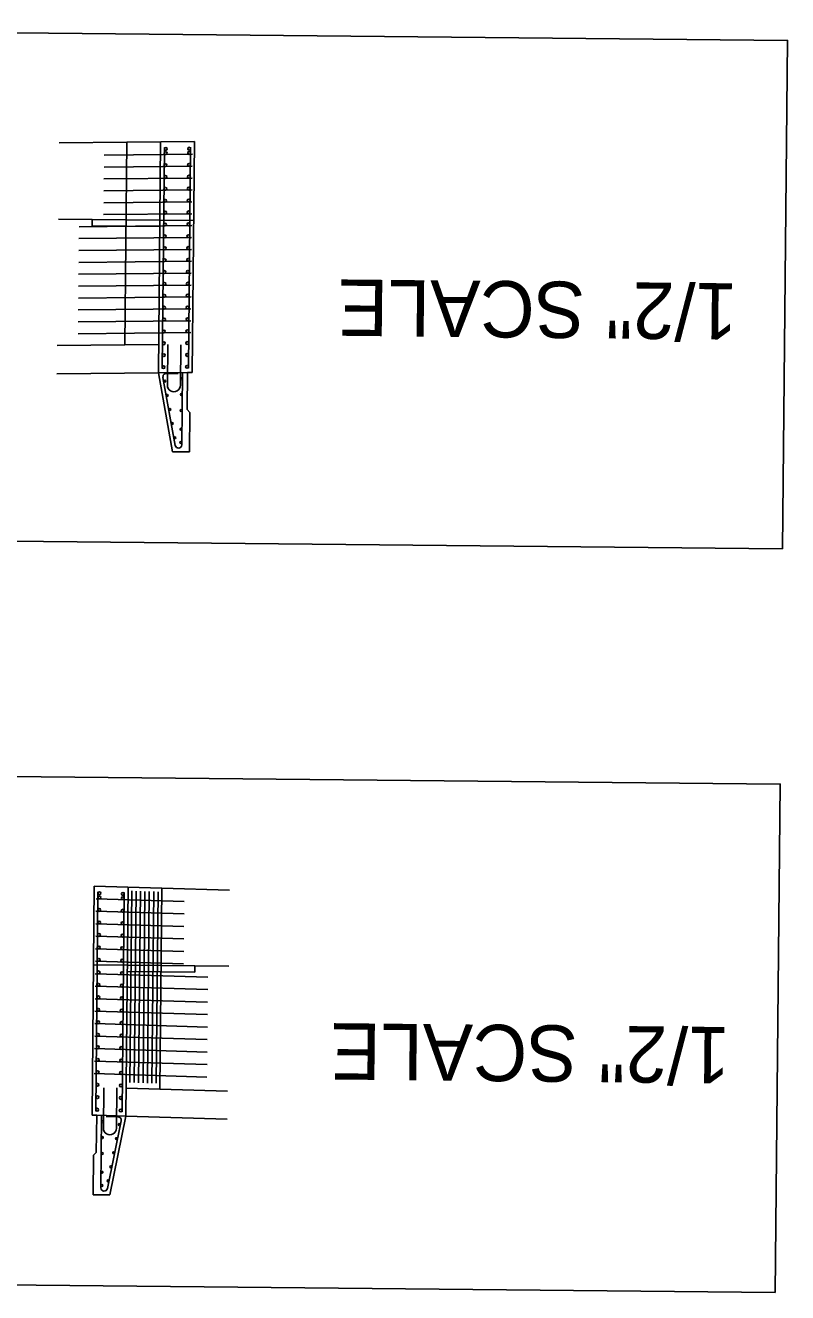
# Model space of a CAD drawing. Extents: x 631918 to 632319, y 373181 to 373282.
# Drawn here: x 631978.4 to 632012.2, y 373182.8 to 373239 of the extents above; entities that cross this region are included whole.
import ezdxf

# ---------------------------------------------------------------- set-up
doc = ezdxf.new("R2010")
doc.units = 0
for name, color, linetype in [('B_Boring', 7, 'Continuous'), ('BD-PROP-COSS', 7, 'Continuous'), ('BD-REMOVE', 7, 'Continuous'), ('R_Border_Scale', 7, 'Continuous'), ('R_Shade Removal', 7, 'Continuous')]:
    doc.layers.add(name, color=color, linetype=linetype)

msp = doc.modelspace()

# ---------------------------------------------------------------- linework, layer by layer
at = {"layer": 'B_Boring'}
for p, q in [((631984.267, 373223.578), (631984.369, 373233.817)), ((631982.822, 373190.59), (631982.923, 373200.757))]:
    msp.add_line(p, q, dxfattribs=at)
at = {"layer": 'BD-PROP-COSS'}
for p, q in [((631981.861, 373233.229), (631985.777, 373233.269)), ((631984.435, 373223.767), (631984.533, 373233.568)), ((631985.602, 373223.777), (631985.699, 373233.58)), ((631981.855, 373232.702), (631985.772, 373232.741)), ((631981.85, 373232.175), (631985.767, 373232.214)), ((631981.845, 373231.648), (631985.761, 373231.687)), ((631981.84, 373231.12), (631985.756, 373231.16)), ((631981.837, 373230.593), (631985.753, 373230.633)), ((631980.748, 373230.055), (631985.748, 373230.105)), ((631980.743, 373229.528), (631985.743, 373229.578)), ((631980.738, 373229.001), (631985.738, 373229.051)), ((631980.733, 373228.474), (631985.732, 373228.524)), ((631980.727, 373227.946), (631985.727, 373227.997)), ((631980.722, 373227.419), (631985.722, 373227.469)), ((631980.717, 373226.892), (631985.717, 373226.942)), ((631980.712, 373226.365), (631985.711, 373226.415)), ((631980.706, 373225.838), (631985.706, 373225.888)), ((631980.701, 373225.31), (631985.701, 373225.361)), ((631984.684, 373224.824), (631984.666, 373223.032)), ((631985.267, 373224.818), (631985.249, 373223.026)), ((631984.473, 373223.373), (631985.017, 373220.355)), ((631985.141, 373223.54), (631984.618, 373223.545)), ((631985.306, 373220.379), (631985.338, 373223.579)), ((631981.491, 373190.816), (631981.588, 373200.547)), ((631985.416, 373200.116), (631981.501, 373200.237)), ((631982.657, 373190.783), (631982.754, 373200.512)), ((631983.003, 373192.086), (631983.088, 373200.585)), ((631983.198, 373192.08), (631983.282, 373200.579)), ((631983.392, 373192.075), (631983.477, 373200.573)), ((631983.587, 373192.069), (631983.671, 373200.567)), ((631983.781, 373192.063), (631983.866, 373200.562)), ((631983.975, 373192.057), (631984.06, 373200.556)), ((631984.17, 373192.051), (631984.254, 373200.55)), ((631985.411, 373199.562), (631981.496, 373199.683)), ((631985.405, 373199.008), (631981.49, 373199.129)), ((631985.4, 373198.454), (631981.485, 373198.575)), ((631985.394, 373197.9), (631981.479, 373198.021)), ((631985.389, 373197.347), (631981.474, 373197.467)), ((631986.466, 373196.759), (631981.468, 373196.913)), ((631986.461, 373196.205), (631981.463, 373196.359)), ((631986.455, 373195.652), (631981.457, 373195.805)), ((631986.45, 373195.098), (631981.452, 373195.251)), ((631986.444, 373194.544), (631981.446, 373194.697)), ((631986.439, 373193.99), (631981.441, 373194.144)), ((631986.433, 373193.436), (631981.435, 373193.59)), ((631986.428, 373192.882), (631981.43, 373193.036)), ((631986.422, 373192.328), (631981.424, 373192.482)), ((631981.847, 373191.85), (631981.829, 373190.059)), ((631982.43, 373191.844), (631982.412, 373190.053)), ((631981.719, 373187.413), (631981.751, 373190.613)), ((631981.947, 373190.57), (631982.47, 373190.565)), ((631982.612, 373190.39), (631982.008, 373187.383))]:
    msp.add_line(p, q, dxfattribs=at)
for points in [[(632011.971, 373215.759), (631944.86, 373216.426), (631945.084, 373238.992), (632012.196, 373238.325)], [(632011.643, 373182.761), (631944.532, 373183.428), (631944.756, 373205.994), (632011.868, 373205.326)]]:
    msp.add_lwpolyline(points, close=True, dxfattribs=at)
for centre, radius in [((631984.593, 373233.318), 0.0625), ((631984.595, 373233.506), 0.0625), ((631985.634, 373233.33), 0.0625), ((631985.636, 373233.517), 0.0625), ((631984.588, 373232.791), 0.0625), ((631985.629, 373232.802), 0.0625), ((631984.582, 373232.264), 0.0625), ((631985.624, 373232.275), 0.0625), ((631984.577, 373231.737), 0.0625), ((631985.619, 373231.748), 0.0625), ((631984.572, 373231.209), 0.0625), ((631985.613, 373231.221), 0.0625), ((631984.567, 373230.682), 0.0625), ((631985.608, 373230.694), 0.0625), ((631984.561, 373230.155), 0.0625), ((631985.603, 373230.166), 0.0625), ((631984.556, 373229.628), 0.0625), ((631985.598, 373229.639), 0.0625), ((631984.551, 373229.101), 0.0625), ((631985.592, 373229.112), 0.0625), ((631984.546, 373228.573), 0.0625), ((631985.587, 373228.585), 0.0625), ((631984.54, 373228.046), 0.0625), ((631985.582, 373228.058), 0.0625), ((631984.535, 373227.519), 0.0625), ((631985.577, 373227.53), 0.0625), ((631984.525, 373226.465), 0.0625), ((631984.53, 373226.992), 0.0625), ((631985.566, 373226.476), 0.0625), ((631985.571, 373227.003), 0.0625), ((631984.519, 373225.937), 0.0625), ((631985.561, 373225.949), 0.0625), ((631984.514, 373225.41), 0.0625), ((631985.556, 373225.422), 0.0625), ((631984.509, 373224.883), 0.0625), ((631985.551, 373224.895), 0.0625), ((631984.504, 373224.356), 0.0625), ((631985.545, 373224.367), 0.0625), ((631984.499, 373223.829), 0.0625), ((631985.54, 373223.84), 0.0625), ((631984.548, 373223.2), 0.0417), ((631985.294, 373223.317), 0.0417), ((631984.661, 373222.574), 0.0417), ((631985.287, 373222.609), 0.0417), ((631984.773, 373221.948), 0.0417), ((631985.28, 373221.901), 0.0417), ((631984.886, 373221.321), 0.0417), ((631985.271, 373221.068), 0.0417), ((631984.998, 373220.695), 0.0417), ((631985.266, 373220.484), 0.0417), ((631981.648, 373200.295), 0.0625), ((631981.65, 373200.482), 0.0625), ((631982.689, 373200.263), 0.0625), ((631982.691, 373200.45), 0.0625), ((631981.642, 373199.741), 0.0625), ((631982.683, 373199.709), 0.0625), ((631981.637, 373199.187), 0.0625), ((631982.678, 373199.155), 0.0625), ((631981.631, 373198.633), 0.0625), ((631982.672, 373198.601), 0.0625), ((631981.626, 373198.079), 0.0625), ((631982.667, 373198.047), 0.0625), ((631981.62, 373197.525), 0.0625), ((631982.661, 373197.493), 0.0625), ((631981.615, 373196.971), 0.0625), ((631982.656, 373196.939), 0.0625), ((631981.609, 373196.417), 0.0625), ((631982.65, 373196.385), 0.0625), ((631981.604, 373195.863), 0.0625), ((631982.645, 373195.831), 0.0625), ((631981.598, 373195.309), 0.0625), ((631982.639, 373195.277), 0.0625), ((631981.593, 373194.756), 0.0625), ((631982.634, 373194.723), 0.0625), ((631981.587, 373194.202), 0.0625), ((631982.628, 373194.169), 0.0625), ((631981.582, 373193.648), 0.0625), ((631982.623, 373193.616), 0.0625), ((631981.576, 373193.094), 0.0625), ((631982.617, 373193.062), 0.0625), ((631981.571, 373192.54), 0.0625), ((631982.612, 373192.508), 0.0625), ((631981.565, 373191.986), 0.0625), ((631982.606, 373191.954), 0.0625), ((631981.56, 373191.432), 0.0625), ((631982.601, 373191.4), 0.0625), ((631981.554, 373190.878), 0.0625), ((631982.595, 373190.846), 0.0625), ((631981.79, 373190.351), 0.0417), ((631982.533, 373190.218), 0.0417), ((631981.783, 373189.642), 0.0417), ((631982.408, 373189.594), 0.0417), ((631981.776, 373188.934), 0.0417), ((631982.283, 373188.971), 0.0417), ((631982.158, 373188.347), 0.0417), ((631981.768, 373188.101), 0.0417), ((631982.034, 373187.723), 0.0417), ((631981.762, 373187.517), 0.0417)]:
    msp.add_circle(centre, radius, dxfattribs=at)
for centre, radius, start, end in [((631984.617, 373223.399), 0.146, 89.4304, 190.2146), ((631984.958, 373223.029), 0.292, 179.4304, 359.4304), ((631985.16, 373220.381), 0.146, 190.2146, 359.4304), ((631982.469, 373190.419), 0.146, 348.6461, 89.4304), ((631982.12, 373190.056), 0.292, 179.4304, 359.4304), ((631981.865, 373187.412), 0.146, 179.4304, 348.6461)]:
    msp.add_arc(centre, radius, start, end, dxfattribs=at)
at = {"layer": 'R_Border_Scale'}
for p, q in [((631982.779, 373224.813), (631982.868, 373233.802)), ((631979.778, 373224.783), (631984.279, 373224.829)), ((631984.267, 373223.578), (631985.559, 373223.591)), ((631984.334, 373191.796), (631984.423, 373200.712)), ((631987.334, 373191.706), (631982.834, 373191.841)), ((631982.822, 373190.59), (631981.531, 373190.629))]:
    msp.add_line(p, q, dxfattribs=at)
at = {"layer": 'R_Shade Removal'}
for p, q in [((631979.868, 373233.772), (631985.869, 373233.832)), ((631985.767, 373223.593), (631985.869, 373233.832)), ((631985.834, 373230.332), (631979.834, 373230.392)), ((631981.332, 373230.099), (631981.334, 373230.377)), ((631984.331, 373230.069), (631981.332, 373230.099)), ((631979.766, 373223.532), (631984.267, 373223.578)), ((631984.267, 373223.578), (631984.899, 373220.071)), ((631985.542, 373221.94), (631985.559, 373223.591)), ((631985.559, 373223.591), (631985.767, 373223.593)), ((631985.666, 373221.814), (631985.542, 373221.94)), ((631985.649, 373220.064), (631985.666, 373221.814)), ((631984.899, 373220.071), (631985.649, 373220.064)), ((631981.323, 373190.635), (631981.424, 373200.801)), ((631987.422, 373200.622), (631981.424, 373200.801)), ((631981.389, 373197.302), (631987.389, 373197.242)), ((631982.886, 373197.009), (631985.886, 373196.979)), ((631985.886, 373196.979), (631985.888, 373197.257)), ((631981.531, 373190.629), (631981.323, 373190.635)), ((631981.514, 373188.978), (631981.531, 373190.629)), ((631982.822, 373190.59), (631982.12, 373187.097)), ((631987.321, 373190.456), (631982.822, 373190.59)), ((631981.371, 373187.105), (631981.388, 373188.855)), ((631981.388, 373188.855), (631981.514, 373188.978)), ((631982.12, 373187.097), (631981.371, 373187.105))]:
    msp.add_line(p, q, dxfattribs=at)

# ---------------------------------------------------------------- texts
at = {"layer": 'BD-REMOVE'}
for p in [(632009.975, 373227.543), (632009.647, 373194.544)]:
    msp.add_text('1/2" SCALE', height=2.5, rotation=179.4304, dxfattribs=at).set_placement(p)

doc.saveas('drawing.dxf')
